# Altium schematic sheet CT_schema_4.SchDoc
size 284 x 147 mm
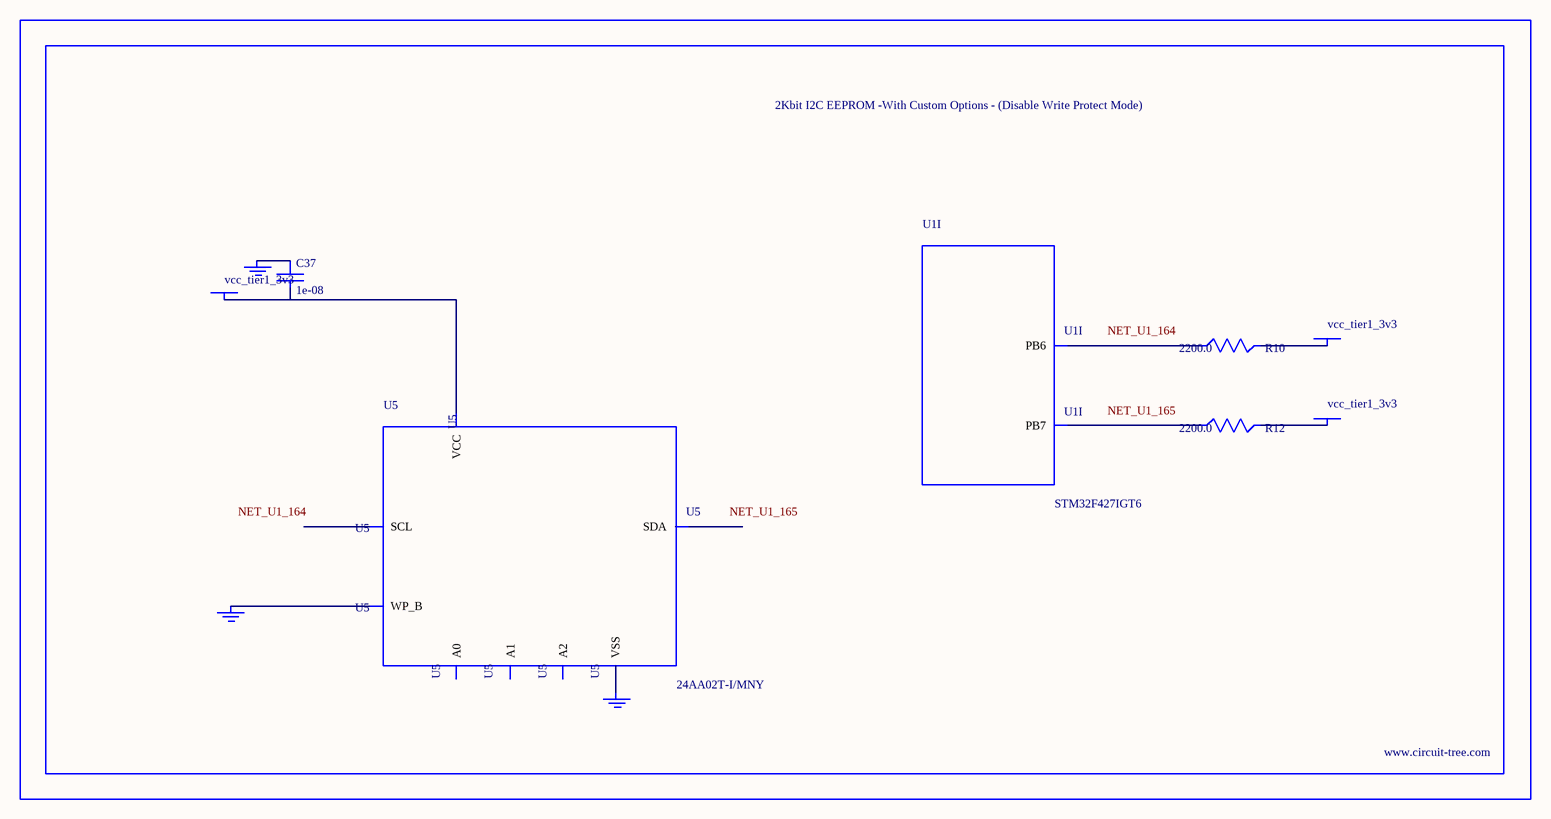
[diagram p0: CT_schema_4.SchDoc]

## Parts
BORDER3  (no value)
C37  1e-08  [C0402]
GND_INSTANCE_3_0  (no value)
GND_INSTANCE_3_1  (no value)
GND_INSTANCE_3_2  (no value)
POWER_INSTANCE_3_0  vcc_tier1_3v3
POWER_INSTANCE_3_1  vcc_tier1_3v3
POWER_INSTANCE_3_2  vcc_tier1_3v3
R10  2200.0  [R0603]
R12  2200.0  [R0603]
U1  STM32F427IGT6  [LQFP176]  (part I of 14)
U5  24AA02T-I/MNY  [TDFN-8/6MM]

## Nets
NetC37_1: C37.1 GND_INSTANCE_3_1.0(GND)
NetC37_2: C37.2 POWER_INSTANCE_3_0.0(PWR) U5.8(VCC)
NetGND_INSTANCE_3_0_0: GND_INSTANCE_3_0.0(GND) U5.7(WP_B)
NetGND_INSTANCE_3_2_0: GND_INSTANCE_3_2.0(GND) U5.4(VSS)
NetPOWER_INSTANCE_3_1_0: POWER_INSTANCE_3_1.0(PWR) R10.2
NetPOWER_INSTANCE_3_2_0: POWER_INSTANCE_3_2.0(PWR) R12.2
NetR10_1: R10.1 U1.164(PB6)
NetR12_1: R12.1 U1.165(PB7)

Not connected (* = marked no-connect by the designer): U5 1(A0) 2(A1) 3(A2) 5(SDA) 6(SCL)

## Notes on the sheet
- Labels drawn without touching a wire or pin: NET_U1_164, NET_U1_165

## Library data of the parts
BORDER3 = BORDER_PAGE3
C37 = C0402C103K3RAC
GND_INSTANCE_3_0-GND_INSTANCE_3_2 = GND
POWER_INSTANCE_3_0-POWER_INSTANCE_3_2 = PWR
R10 R12 = RC0603JR-072K2L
